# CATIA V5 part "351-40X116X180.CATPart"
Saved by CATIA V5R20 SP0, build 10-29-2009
Part number: 351-40X116X180
Definition: NONE
Nomenclature: 351-40X116X180
Source: Unknown
Description: 351-40X116X180
Bounding box of the stored display mesh (mm): x -8 to 172, y -26 to 26, z -26 to 26
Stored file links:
  C:\Users\Utente\Desktop\IO LAVORO\3D X SITO CF\X SITO\PLASTICA\351\351-40X116X180.CATPart

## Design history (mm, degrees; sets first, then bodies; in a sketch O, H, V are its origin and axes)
Body1 "351-40X116X180" (main body)
  Solid1: solid without history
